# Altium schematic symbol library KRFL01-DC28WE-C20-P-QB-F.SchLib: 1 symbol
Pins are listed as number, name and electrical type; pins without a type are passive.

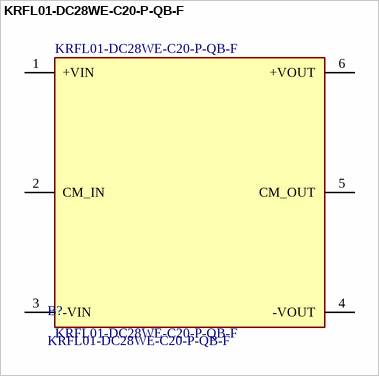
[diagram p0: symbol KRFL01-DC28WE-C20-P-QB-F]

## KRFL01-DC28WE-C20-P-QB-F
designator B?
20Aout Passive Quarter EMI Filter Brick with Flanged Option; MFG: KOLT
footprint KRFL01-DC28WE-C20-P-QB-F
pins: 1 +VIN, 2 CM_IN, 3 -VIN, 4 -VOUT, 5 CM_OUT, 6 +VOUT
